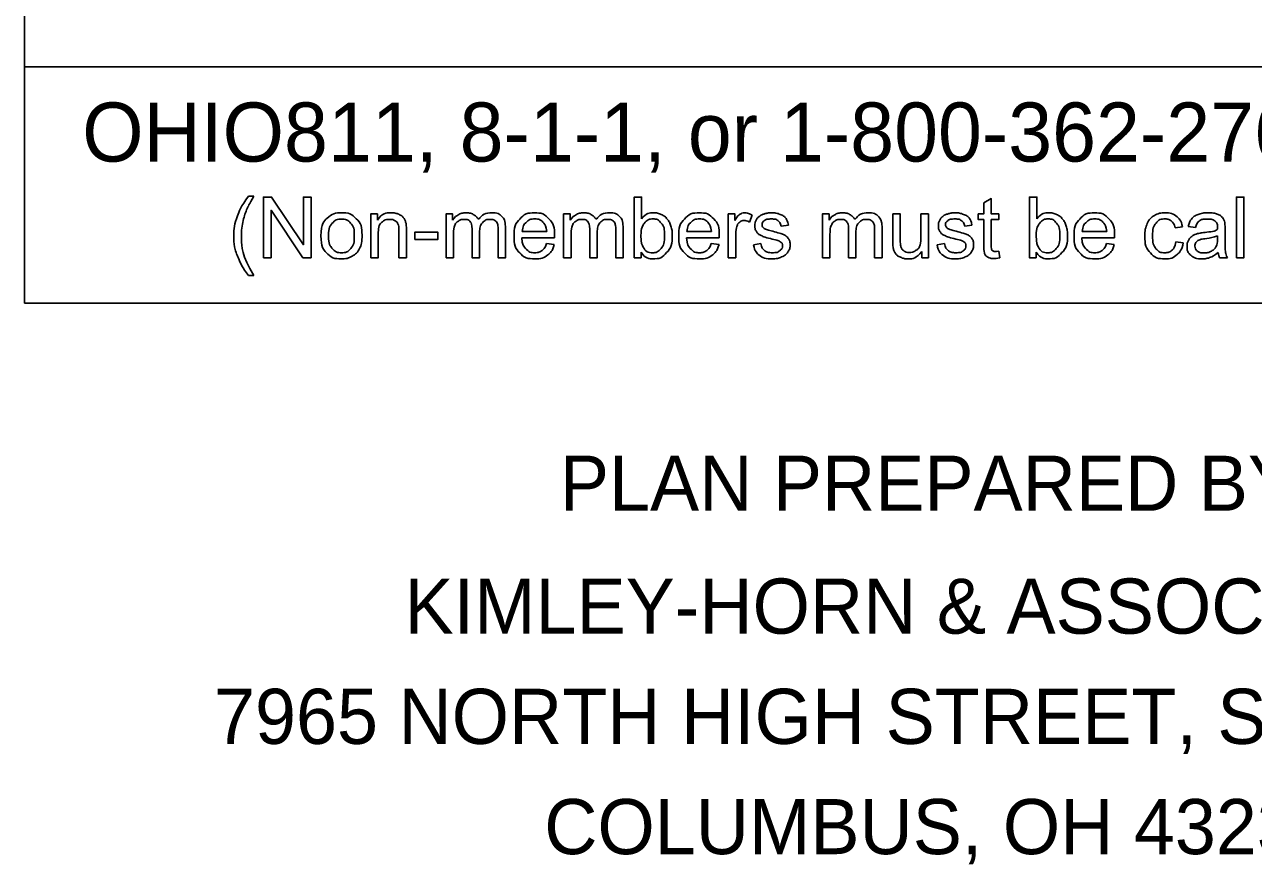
# Model space of a CAD drawing. Extents: x 0 to 72, y -85 to 22.
# Drawn here: x 42.946 to 46.068, y -11.977 to -9.844 of the extents above; entities that cross this region are included whole.
import ezdxf

# ---------------------------------------------------------------- set-up
doc = ezdxf.new("R2010")
doc.units = 0
doc.layers.add('GM_X_Township', color=7, linetype='Continuous')

msp = doc.modelspace()

# ---------------------------------------------------------------- linework, layer by layer
at = {"layer": 'GM_X_Township'}
for p, q in [((42.9464, -10.5516), (42.9464, -7.5516)), ((47.6964, -9.9516), (42.9464, -9.9516)), ((47.6964, -10.5516), (42.9464, -10.5516))]:
    msp.add_line(p, q, dxfattribs=at)
for points in [[(43.5153, -10.2797), (43.5288, -10.2797)], [(43.553, -10.4362), (43.553, -10.2822), (43.5739, -10.2822), (43.6549, -10.4032), (43.6549, -10.2822), (43.6744, -10.2822), (43.6744, -10.4362), (43.6535, -10.4362), (43.5725, -10.3153), (43.5725, -10.4362), (43.553, -10.4362)], [(44.5125, -10.4362), (44.495, -10.4362), (44.495, -10.2822), (44.5139, -10.2822), (44.5139, -10.3371)], [(45.3832, -10.4036), (45.3832, -10.3393), (45.3692, -10.3393), (45.3692, -10.3246), (45.3832, -10.3246), (45.3832, -10.297), (45.4021, -10.2856), (45.4021, -10.3246), (45.421, -10.3246), (45.421, -10.3393), (45.4021, -10.3393), (45.4021, -10.4047)], [(45.5166, -10.4362), (45.4991, -10.4362), (45.4991, -10.2822), (45.518, -10.2822), (45.518, -10.3371)], [(46.025, -10.4362), (46.025, -10.2822), (46.0439, -10.2822), (46.0439, -10.4362), (46.025, -10.4362)], [(43.8258, -10.4362), (43.8258, -10.3246), (43.8428, -10.3246), (43.8428, -10.3405)], [(44.017, -10.4362), (44.017, -10.3246), (44.0339, -10.3246), (44.0339, -10.3404)], [(44.3158, -10.4362), (44.3158, -10.3246), (44.3327, -10.3246), (44.3327, -10.3404)], [(44.7341, -10.4362), (44.7341, -10.3246), (44.7511, -10.3246), (44.7511, -10.3415)], [(44.7946, -10.3282), (44.788, -10.3457)], [(44.9733, -10.4362), (44.9733, -10.3246), (44.9902, -10.3246), (44.9902, -10.3404)], [(45.1521, -10.3937), (45.1521, -10.3246), (45.1709, -10.3246), (45.1709, -10.3865)], [(45.2235, -10.3844), (45.2235, -10.3246), (45.2424, -10.3246), (45.2424, -10.4362), (45.2255, -10.4362)], [(44.1022, -10.3714), (44.1022, -10.4362), (44.0833, -10.4362), (44.0833, -10.3638)], [(44.1683, -10.3597), (44.1683, -10.4362), (44.1494, -10.4362), (44.1494, -10.366)], [(44.401, -10.3714), (44.401, -10.4362), (44.3821, -10.4362), (44.3821, -10.3638)], [(44.4671, -10.3597), (44.4671, -10.4362), (44.4482, -10.4362), (44.4482, -10.366)], [(44.8869, -10.3535), (44.8683, -10.356)], [(45.0585, -10.3714), (45.0585, -10.4362), (45.0396, -10.4362), (45.0396, -10.3638)], [(45.1246, -10.3597), (45.1246, -10.4362), (45.1057, -10.4362), (45.1057, -10.366)], [(45.3531, -10.3535), (45.3346, -10.356)], [(45.8879, -10.3575), (45.8695, -10.3603)], [(45.9212, -10.359), (45.9027, -10.3565)], [(43.8447, -10.3753), (43.8447, -10.4362), (43.8258, -10.4362)], [(43.9164, -10.3676), (43.9164, -10.4362), (43.8975, -10.4362), (43.8975, -10.3684)], [(43.9379, -10.39), (43.9379, -10.371), (43.9961, -10.371), (43.9961, -10.39), (43.9379, -10.39)], [(44.0359, -10.3784), (44.0359, -10.4362), (44.017, -10.4362)], [(44.2926, -10.3853), (44.2094, -10.3853)], [(44.2104, -10.3698), (44.2728, -10.3698)], [(44.3347, -10.3784), (44.3347, -10.4362), (44.3158, -10.4362)], [(44.7111, -10.3853), (44.6278, -10.3853)], [(44.6289, -10.3698), (44.6912, -10.3698)], [(44.753, -10.3778), (44.753, -10.4362), (44.7341, -10.4362)], [(44.9922, -10.3784), (44.9922, -10.4362), (44.9733, -10.4362)], [(45.7152, -10.3853), (45.632, -10.3853)], [(45.6331, -10.3698), (45.6954, -10.3698)], [(45.977, -10.3872), (45.9771, -10.3802)], [(45.9961, -10.3643), (45.9961, -10.3895)], [(44.2726, -10.4002), (44.2921, -10.4027)], [(44.5125, -10.4223), (44.5125, -10.4362)], [(44.691, -10.4002), (44.7105, -10.4027)], [(44.7983, -10.4029), (44.8169, -10.4)], [(45.2255, -10.4362), (45.2255, -10.4198)], [(45.2645, -10.4029), (45.2832, -10.4)], [(45.421, -10.4194), (45.4237, -10.4361)], [(45.5166, -10.4223), (45.5166, -10.4362)], [(45.6952, -10.4002), (45.7147, -10.4027)], [(45.8711, -10.3954), (45.8897, -10.3979)], [(46.0021, -10.4362), (45.9824, -10.4362)], [(43.5288, -10.4815), (43.5153, -10.4815)]]:
    msp.add_lwpolyline(points, dxfattribs=at)
for points, degree in [([(43.5153, -10.4815), (43.4997, -10.4618), (43.4888, -10.4353), (43.478, -10.4089), (43.478, -10.3805), (43.478, -10.3555), (43.4861, -10.3326), (43.4956, -10.306), (43.5153, -10.2797)], 3), ([(43.5288, -10.2797), (43.5161, -10.3015), (43.5121, -10.3109), (43.5057, -10.3253), (43.502, -10.3411), (43.4975, -10.3607), (43.4975, -10.3806), (43.4975, -10.4311), (43.5288, -10.4815)], 3), ([(43.6991, -10.3804), (43.6991, -10.3494), (43.7164, -10.3345), (43.7307, -10.3221), (43.7514, -10.3221), (43.7744, -10.3221), (43.789, -10.3372), (43.8036, -10.3523), (43.8036, -10.3788), (43.8036, -10.4004), (43.7972, -10.4127), (43.7907, -10.4251), (43.7784, -10.4319), (43.766, -10.4387), (43.7514, -10.4387), (43.728, -10.4387), (43.7136, -10.4237), (43.6991, -10.4087), (43.6991, -10.3804)], 3), ([(43.8428, -10.3405), (43.8551, -10.3221), (43.8783, -10.3221), (43.8884, -10.3221), (43.8968, -10.3258), (43.9053, -10.3294), (43.9095, -10.3353), (43.9137, -10.3412), (43.9154, -10.3493), (43.9164, -10.3545), (43.9164, -10.3676)], 3), ([(44.0339, -10.3404), (44.0391, -10.3322), (44.0479, -10.3271), (44.0566, -10.3221), (44.0677, -10.3221), (44.0801, -10.3221), (44.0881, -10.3273), (44.096, -10.3325), (44.0993, -10.3417), (44.1125, -10.3221), (44.1338, -10.3221), (44.1504, -10.3221), (44.1593, -10.3313), (44.1683, -10.3405), (44.1683, -10.3597)], 3), ([(44.2921, -10.4027), (44.2875, -10.4198), (44.275, -10.4292), (44.2625, -10.4387), (44.243, -10.4387), (44.2186, -10.4387), (44.2042, -10.4236), (44.1899, -10.4086), (44.1899, -10.3814), (44.1899, -10.3532), (44.2044, -10.3377), (44.2189, -10.3221), (44.242, -10.3221), (44.2644, -10.3221), (44.2785, -10.3374), (44.2927, -10.3526), (44.2927, -10.3803), (44.2927, -10.3819), (44.2926, -10.3853)], 3), ([(44.3327, -10.3404), (44.338, -10.3322), (44.3467, -10.3271), (44.3554, -10.3221), (44.3666, -10.3221), (44.379, -10.3221), (44.3869, -10.3273), (44.3948, -10.3325), (44.3981, -10.3417), (44.4114, -10.3221), (44.4326, -10.3221), (44.4492, -10.3221), (44.4582, -10.3313), (44.4671, -10.3405), (44.4671, -10.3597)], 3), ([(44.5139, -10.3371), (44.5258, -10.3221), (44.5444, -10.3221), (44.5547, -10.3221), (44.5639, -10.3263), (44.5731, -10.3304), (44.579, -10.3379), (44.585, -10.3455), (44.5883, -10.3561), (44.5917, -10.3667), (44.5917, -10.3787), (44.5917, -10.4074), (44.5775, -10.4231), (44.5633, -10.4387), (44.5435, -10.4387), (44.5237, -10.4387), (44.5125, -10.4223)], 3), ([(44.7105, -10.4027), (44.7059, -10.4198), (44.6934, -10.4292), (44.6809, -10.4387), (44.6615, -10.4387), (44.637, -10.4387), (44.6227, -10.4236), (44.6084, -10.4086), (44.6084, -10.3814), (44.6084, -10.3532), (44.6229, -10.3377), (44.6373, -10.3221), (44.6605, -10.3221), (44.6828, -10.3221), (44.697, -10.3374), (44.7112, -10.3526), (44.7112, -10.3803), (44.7112, -10.3819), (44.7111, -10.3853)], 3), ([(44.7511, -10.3415), (44.7576, -10.3297), (44.7631, -10.3259), (44.7686, -10.3221), (44.7752, -10.3221), (44.7848, -10.3221), (44.7946, -10.3282)], 3), ([(44.8169, -10.4), (44.8185, -10.4112), (44.8257, -10.4172), (44.833, -10.4232), (44.8459, -10.4232), (44.859, -10.4232), (44.8653, -10.4179), (44.8716, -10.4126), (44.8716, -10.4054), (44.8716, -10.399), (44.866, -10.3953), (44.8621, -10.3928), (44.8467, -10.3889), (44.8259, -10.3837), (44.8178, -10.3798), (44.8098, -10.376), (44.8056, -10.3692), (44.8014, -10.3625), (44.8014, -10.3543), (44.8014, -10.3468), (44.8049, -10.3405), (44.8083, -10.3341), (44.8142, -10.3299), (44.8186, -10.3267), (44.8262, -10.3244), (44.8339, -10.3221), (44.8426, -10.3221), (44.8557, -10.3221), (44.8657, -10.3259), (44.8756, -10.3297), (44.8804, -10.3362), (44.8851, -10.3427), (44.8869, -10.3535)], 3), ([(44.9902, -10.3404), (44.9954, -10.3322), (45.0041, -10.3271), (45.0129, -10.3221), (45.024, -10.3221), (45.0364, -10.3221), (45.0443, -10.3273), (45.0523, -10.3325), (45.0555, -10.3417), (45.0688, -10.3221), (45.0901, -10.3221), (45.1067, -10.3221), (45.1156, -10.3313), (45.1246, -10.3405), (45.1246, -10.3597)], 3), ([(45.2832, -10.4), (45.2847, -10.4112), (45.292, -10.4172), (45.2992, -10.4232), (45.3121, -10.4232), (45.3252, -10.4232), (45.3315, -10.4179), (45.3379, -10.4126), (45.3379, -10.4054), (45.3379, -10.399), (45.3323, -10.3953), (45.3284, -10.3928), (45.3129, -10.3889), (45.2921, -10.3837), (45.284, -10.3798), (45.276, -10.376), (45.2718, -10.3692), (45.2677, -10.3625), (45.2677, -10.3543), (45.2677, -10.3468), (45.2711, -10.3405), (45.2745, -10.3341), (45.2804, -10.3299), (45.2848, -10.3267), (45.2925, -10.3244), (45.3001, -10.3221), (45.3088, -10.3221), (45.322, -10.3221), (45.3319, -10.3259), (45.3419, -10.3297), (45.3466, -10.3362), (45.3513, -10.3427), (45.3531, -10.3535)], 3), ([(45.518, -10.3371), (45.53, -10.3221), (45.5486, -10.3221), (45.5589, -10.3221), (45.5681, -10.3263), (45.5773, -10.3304), (45.5832, -10.3379), (45.5891, -10.3455), (45.5925, -10.3561), (45.5959, -10.3667), (45.5959, -10.3787), (45.5959, -10.4074), (45.5817, -10.4231), (45.5675, -10.4387), (45.5476, -10.4387), (45.5279, -10.4387), (45.5166, -10.4223)], 3), ([(45.7147, -10.4027), (45.7101, -10.4198), (45.6976, -10.4292), (45.6851, -10.4387), (45.6657, -10.4387), (45.6412, -10.4387), (45.6269, -10.4236), (45.6125, -10.4086), (45.6125, -10.3814), (45.6125, -10.3532), (45.627, -10.3377), (45.6415, -10.3221), (45.6646, -10.3221), (45.687, -10.3221), (45.7012, -10.3374), (45.7153, -10.3526), (45.7153, -10.3803), (45.7153, -10.3819), (45.7152, -10.3853)], 3), ([(45.8897, -10.3979), (45.8866, -10.417), (45.8741, -10.4279), (45.8615, -10.4387), (45.8432, -10.4387), (45.8203, -10.4387), (45.8064, -10.4237), (45.7925, -10.4088), (45.7925, -10.3808), (45.7925, -10.3628), (45.7985, -10.3492), (45.8044, -10.3357), (45.8167, -10.3289), (45.8289, -10.3221), (45.8433, -10.3221), (45.8615, -10.3221), (45.8731, -10.3313), (45.8846, -10.3405), (45.8879, -10.3575)], 3), ([(45.9027, -10.3565), (45.9052, -10.3447), (45.911, -10.3373), (45.9168, -10.33), (45.9277, -10.3261), (45.9386, -10.3221), (45.953, -10.3221), (45.9672, -10.3221), (45.9762, -10.3255), (45.9851, -10.3289), (45.9893, -10.334), (45.9935, -10.3391), (45.9952, -10.3468), (45.9961, -10.3517), (45.9961, -10.3643)], 3), ([(43.7186, -10.3804), (43.7186, -10.4019), (43.728, -10.4125), (43.7373, -10.4232), (43.7514, -10.4232), (43.7655, -10.4232), (43.7748, -10.4125), (43.7841, -10.4018), (43.7841, -10.3798), (43.7841, -10.3591), (43.7747, -10.3484), (43.7654, -10.3378), (43.7514, -10.3378), (43.7373, -10.3378), (43.728, -10.3484), (43.7186, -10.359), (43.7186, -10.3804)], 3), ([(43.8975, -10.3684), (43.8975, -10.3569), (43.8953, -10.3511), (43.8931, -10.3454), (43.8875, -10.342), (43.8819, -10.3386), (43.8743, -10.3386), (43.8622, -10.3386), (43.8535, -10.3462), (43.8447, -10.3539), (43.8447, -10.3753)], 3), ([(44.0833, -10.3638), (44.0833, -10.3512), (44.0787, -10.3449), (44.0741, -10.3386), (44.0635, -10.3386), (44.0555, -10.3386), (44.0488, -10.3428), (44.042, -10.347), (44.0389, -10.3551), (44.0359, -10.3632), (44.0359, -10.3784)], 3), ([(44.1494, -10.366), (44.1494, -10.3546), (44.1475, -10.3497), (44.1457, -10.3447), (44.1409, -10.3416), (44.136, -10.3386), (44.1295, -10.3386), (44.1178, -10.3386), (44.11, -10.3464), (44.1022, -10.3542), (44.1022, -10.3714)], 3), ([(44.2728, -10.3698), (44.2715, -10.3557), (44.2656, -10.3486), (44.2566, -10.3376), (44.2422, -10.3376), (44.2292, -10.3376), (44.2203, -10.3464), (44.2114, -10.3551), (44.2104, -10.3698)], 3), ([(44.3821, -10.3638), (44.3821, -10.3512), (44.3775, -10.3449), (44.3729, -10.3386), (44.3624, -10.3386), (44.3544, -10.3386), (44.3476, -10.3428), (44.3408, -10.347), (44.3378, -10.3551), (44.3347, -10.3632), (44.3347, -10.3784)], 3), ([(44.4482, -10.366), (44.4482, -10.3546), (44.4464, -10.3497), (44.4446, -10.3447), (44.4397, -10.3416), (44.4349, -10.3386), (44.4284, -10.3386), (44.4166, -10.3386), (44.4088, -10.3464), (44.401, -10.3542), (44.401, -10.3714)], 3), ([(44.5122, -10.3796), (44.5122, -10.3997), (44.5177, -10.4086), (44.5266, -10.4232), (44.5418, -10.4232), (44.5542, -10.4232), (44.5632, -10.4124), (44.5722, -10.4017), (44.5722, -10.3803), (44.5722, -10.3585), (44.5636, -10.348), (44.5549, -10.3376), (44.5426, -10.3376), (44.5303, -10.3376), (44.5212, -10.3484), (44.5122, -10.3592), (44.5122, -10.3796)], 3), ([(44.6912, -10.3698), (44.69, -10.3557), (44.6841, -10.3486), (44.675, -10.3376), (44.6606, -10.3376), (44.6476, -10.3376), (44.6387, -10.3464), (44.6298, -10.3551), (44.6289, -10.3698)], 3), ([(44.788, -10.3457), (44.7811, -10.3416), (44.7742, -10.3416), (44.768, -10.3416), (44.7631, -10.3454), (44.7582, -10.3491), (44.7561, -10.3557), (44.753, -10.3658), (44.753, -10.3778)], 3), ([(44.8683, -10.356), (44.8671, -10.3473), (44.861, -10.3425), (44.855, -10.3376), (44.8439, -10.3376), (44.8309, -10.3376), (44.8253, -10.342), (44.8198, -10.3463), (44.8198, -10.3521), (44.8198, -10.3557), (44.8221, -10.3587), (44.8244, -10.3617), (44.8293, -10.3637), (44.8322, -10.3648), (44.8461, -10.3686), (44.8661, -10.3739), (44.8741, -10.3773), (44.8821, -10.3808), (44.8866, -10.3873), (44.8911, -10.3938), (44.8911, -10.4034), (44.8911, -10.4129), (44.8856, -10.4212), (44.8801, -10.4296), (44.8696, -10.4341), (44.8592, -10.4387), (44.8461, -10.4387), (44.8243, -10.4387), (44.8129, -10.4297), (44.8014, -10.4206), (44.7983, -10.4029)], 3), ([(45.0396, -10.3638), (45.0396, -10.3512), (45.035, -10.3449), (45.0303, -10.3386), (45.0198, -10.3386), (45.0118, -10.3386), (45.005, -10.3428), (44.9983, -10.347), (44.9952, -10.3551), (44.9922, -10.3632), (44.9922, -10.3784)], 3), ([(45.1057, -10.366), (45.1057, -10.3546), (45.1038, -10.3497), (45.102, -10.3447), (45.0972, -10.3416), (45.0923, -10.3386), (45.0858, -10.3386), (45.074, -10.3386), (45.0663, -10.3464), (45.0585, -10.3542), (45.0585, -10.3714)], 3), ([(45.3346, -10.356), (45.3333, -10.3473), (45.3273, -10.3425), (45.3212, -10.3376), (45.3102, -10.3376), (45.2971, -10.3376), (45.2916, -10.342), (45.286, -10.3463), (45.286, -10.3521), (45.286, -10.3557), (45.2883, -10.3587), (45.2906, -10.3617), (45.2956, -10.3637), (45.2984, -10.3648), (45.3123, -10.3686), (45.3324, -10.3739), (45.3403, -10.3773), (45.3483, -10.3808), (45.3528, -10.3873), (45.3573, -10.3938), (45.3573, -10.4034), (45.3573, -10.4129), (45.3518, -10.4212), (45.3463, -10.4296), (45.3359, -10.4341), (45.3255, -10.4387), (45.3123, -10.4387), (45.2905, -10.4387), (45.2791, -10.4297), (45.2677, -10.4206), (45.2645, -10.4029)], 3), ([(45.5164, -10.3796), (45.5164, -10.3997), (45.5218, -10.4086), (45.5308, -10.4232), (45.546, -10.4232), (45.5583, -10.4232), (45.5674, -10.4124), (45.5764, -10.4017), (45.5764, -10.3803), (45.5764, -10.3585), (45.5677, -10.348), (45.5591, -10.3376), (45.5468, -10.3376), (45.5344, -10.3376), (45.5254, -10.3484), (45.5164, -10.3592), (45.5164, -10.3796)], 3), ([(45.6954, -10.3698), (45.6941, -10.3557), (45.6882, -10.3486), (45.6792, -10.3376), (45.6648, -10.3376), (45.6518, -10.3376), (45.6429, -10.3464), (45.634, -10.3551), (45.6331, -10.3698)], 3), ([(45.8695, -10.3603), (45.8668, -10.349), (45.8602, -10.3433), (45.8535, -10.3376), (45.8441, -10.3376), (45.8298, -10.3376), (45.8209, -10.3479), (45.812, -10.3581), (45.812, -10.3803), (45.812, -10.4028), (45.8206, -10.413), (45.8292, -10.4232), (45.8431, -10.4232), (45.8542, -10.4232), (45.8617, -10.4164), (45.8691, -10.4096), (45.8711, -10.3954)], 3), ([(45.9786, -10.4225), (45.9681, -10.4314), (45.9584, -10.435), (45.9486, -10.4387), (45.9375, -10.4387), (45.9191, -10.4387), (45.9093, -10.4297), (45.8994, -10.4208), (45.8994, -10.4068), (45.8994, -10.3986), (45.9031, -10.3919), (45.9069, -10.3851), (45.9129, -10.381), (45.9189, -10.3769), (45.9265, -10.3748), (45.9321, -10.3733), (45.9433, -10.372), (45.9662, -10.3692), (45.977, -10.3655), (45.9771, -10.3616), (45.9771, -10.3605), (45.9771, -10.3489), (45.9718, -10.3442), (45.9645, -10.3378), (45.9503, -10.3378), (45.937, -10.3378), (45.9306, -10.3424), (45.9243, -10.3471), (45.9212, -10.359)], 3), ([(44.2094, -10.3853), (44.2104, -10.4037), (44.2198, -10.4134), (44.2292, -10.4232), (44.2431, -10.4232), (44.2535, -10.4232), (44.2609, -10.4177), (44.2683, -10.4122), (44.2726, -10.4002)], 3), ([(44.6278, -10.3853), (44.6289, -10.4037), (44.6382, -10.4134), (44.6476, -10.4232), (44.6616, -10.4232), (44.672, -10.4232), (44.6793, -10.4177), (44.6867, -10.4122), (44.691, -10.4002)], 3), ([(45.2255, -10.4198), (45.2125, -10.4387), (45.1902, -10.4387), (45.1803, -10.4387), (45.1717, -10.4349), (45.1632, -10.4311), (45.159, -10.4254), (45.1549, -10.4197), (45.1532, -10.4114), (45.1521, -10.4058), (45.1521, -10.3937)], 3), ([(45.1709, -10.3865), (45.1709, -10.4013), (45.1721, -10.4064), (45.1739, -10.4139), (45.1797, -10.4181), (45.1854, -10.4224), (45.1939, -10.4224), (45.2024, -10.4224), (45.2099, -10.418), (45.2173, -10.4137), (45.2204, -10.4062), (45.2235, -10.3987), (45.2235, -10.3844)], 3), ([(45.632, -10.3853), (45.6331, -10.4037), (45.6424, -10.4134), (45.6518, -10.4232), (45.6658, -10.4232), (45.6762, -10.4232), (45.6835, -10.4177), (45.6909, -10.4122), (45.6952, -10.4002)], 3), ([(45.9771, -10.3802), (45.9668, -10.3844), (45.9462, -10.3874), (45.9345, -10.3891), (45.9297, -10.3912), (45.9248, -10.3933), (45.9222, -10.3973), (45.9196, -10.4013), (45.9196, -10.4063), (45.9196, -10.4138), (45.9253, -10.4189), (45.931, -10.4239), (45.942, -10.4239), (45.953, -10.4239), (45.9615, -10.4191), (45.97, -10.4144), (45.974, -10.4061), (45.977, -10.3997), (45.977, -10.3872)], 3), ([(45.9961, -10.3895), (45.9961, -10.4158), (45.9973, -10.4228), (45.9985, -10.4298), (46.0021, -10.4362)], 3), ([(45.4237, -10.4361), (45.4157, -10.4378), (45.4094, -10.4378), (45.3991, -10.4378), (45.3935, -10.4345), (45.3878, -10.4312), (45.3855, -10.4259), (45.3832, -10.4206), (45.3832, -10.4036)], 3), ([(45.4021, -10.4047), (45.4021, -10.4128), (45.4031, -10.4151), (45.4041, -10.4174), (45.4063, -10.4188), (45.4085, -10.4202), (45.4127, -10.4202), (45.4158, -10.4202), (45.421, -10.4194)], 3), ([(45.9824, -10.4362), (45.9795, -10.4304), (45.9786, -10.4225)], 2)]:
    msp.add_open_spline(points, degree=degree, dxfattribs=at)

# ---------------------------------------------------------------- texts
for s, height, p in [('OHIO811, 8-1-1, or 1-800-362-2764', 0.15, (43.0928, -10.1918)), ('PLAN PREPARED BY:', 0.14, (44.3062, -11.0787)), ('KIMLEY-HORN & ASSOCIATES', 0.14, (43.9116, -11.3907)), ('7965 NORTH HIGH STREET, SUITE 200', 0.14, (43.4277, -11.6707)), ('COLUMBUS, OH 43235', 0.14, (44.2665, -11.9507))]:
    msp.add_text(s, height=height, dxfattribs=at).set_placement(p)

doc.saveas('drawing.dxf')
